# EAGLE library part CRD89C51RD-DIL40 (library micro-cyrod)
CRD89C51RD series 8 - bit single chip micro controller unit (MCU) with 64KB flash & 1K byte RAM embedded. Auto generated by make-symbol-device-package-bsdl.ulp Rev. 35 Source: CRD89C51RD_v001.pdf
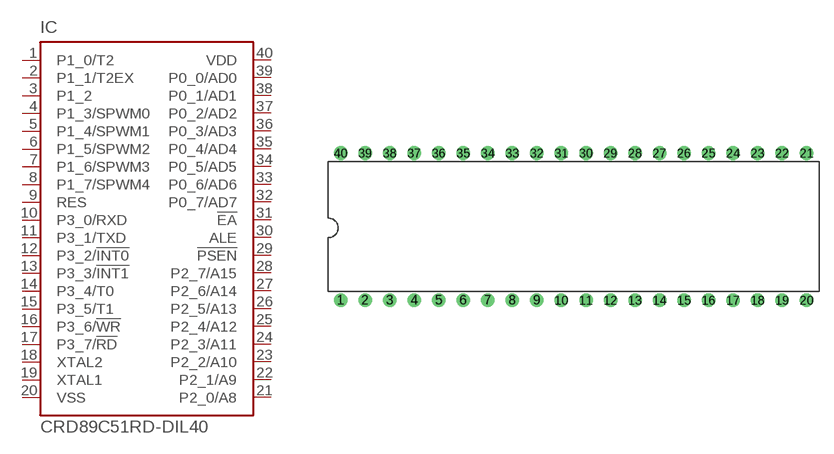
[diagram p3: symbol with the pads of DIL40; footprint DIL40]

Designator prefix IC

## CRD89C51RD-DIL40 (OC_FARNELL: unknown; OC_NEWARK: unknown)  [DIL40]
1  P1_0/T2
2  P1_1/T2EX
3  P1_2
4  P1_3/SPWM0
5  P1_4/SPWM1
6  P1_5/SPWM2
7  P1_6/SPWM3
8  P1_7/SPWM4
9  RES  in
10  P3_0/RXD
11  P3_1/TXD
12  P3_2/!INT0
13  P3_3/!INT1
14  P3_4/T0
15  P3_5/T1
16  P3_6/!WR
17  P3_7/!RD
18  XTAL2  out
19  XTAL1  in
20  VSS  pwr
21  P2_0/A8
22  P2_1/A9
23  P2_2/A10
24  P2_3/A11
25  P2_4/A12
26  P2_5/A13
27  P2_6/A14
28  P2_7/A15
29  !PSEN  out
30  ALE  out
31  !EA  in
32  P0_7/AD7
33  P0_6/AD6
34  P0_5/AD5
35  P0_4/AD4
36  P0_3/AD3
37  P0_2/AD2
38  P0_1/AD1
39  P0_0/AD0
40  VDD  pwr

## Footprint DIL40 (pad centres in mm)
Dual In Line Package 600mil
drill 0.8 pad 1.4 round: 1 -24.13,-7.62; 2 -21.59,-7.62; 3 -19.05,-7.62; 4 -16.51,-7.62; 5 -13.97,-7.62; 6 -11.43,-7.62; 7 -8.89,-7.62; 8 -6.35,-7.62; 9 -3.81,-7.62; 10 -1.27,-7.62; 11 1.27,-7.62; 12 3.81,-7.62; 13 6.35,-7.62; 14 8.89,-7.62; 15 11.43,-7.62; 16 13.97,-7.62; 17 16.51,-7.62; 18 19.05,-7.62; 19 21.59,-7.62; 20 24.13,-7.62; 21 24.13,7.62; 22 21.59,7.62; 23 19.05,7.62; 24 16.51,7.62; 25 13.97,7.62; 26 11.43,7.62; 27 8.89,7.62; 28 6.35,7.62; 29 3.81,7.62; 30 1.27,7.62; 31 -1.27,7.62; 32 -3.81,7.62; 33 -6.35,7.62; 34 -8.89,7.62; 35 -11.43,7.62; 36 -13.97,7.62; 37 -16.51,7.62; 38 -19.05,7.62; 39 -21.59,7.62; 40 -24.13,7.62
